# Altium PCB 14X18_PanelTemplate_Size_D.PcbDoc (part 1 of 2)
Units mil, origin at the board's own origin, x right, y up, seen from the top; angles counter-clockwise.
Board outline 18000 x 14000 mil, 2 copper layers (Top Layer, Bottom Layer); 52 components, 1 nets, 312 pads, 0 vias.
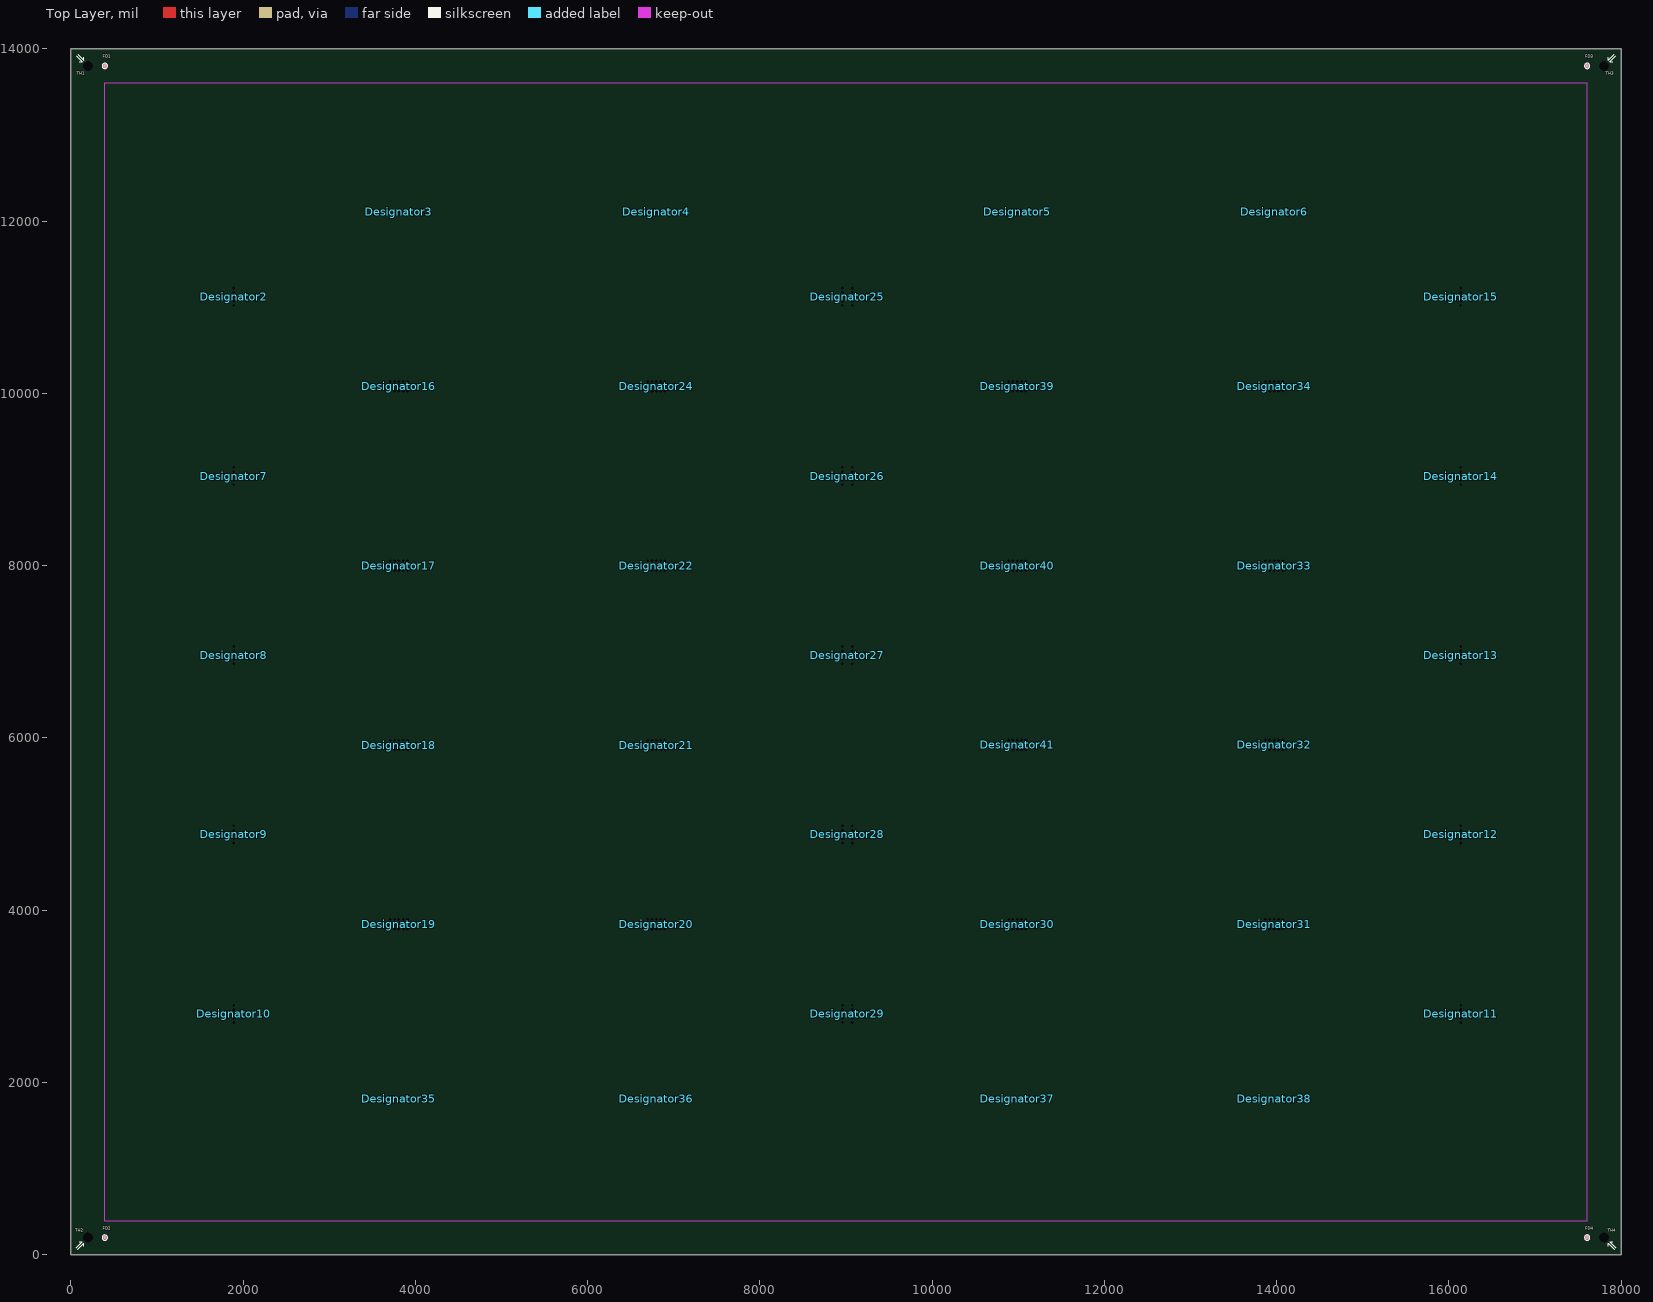
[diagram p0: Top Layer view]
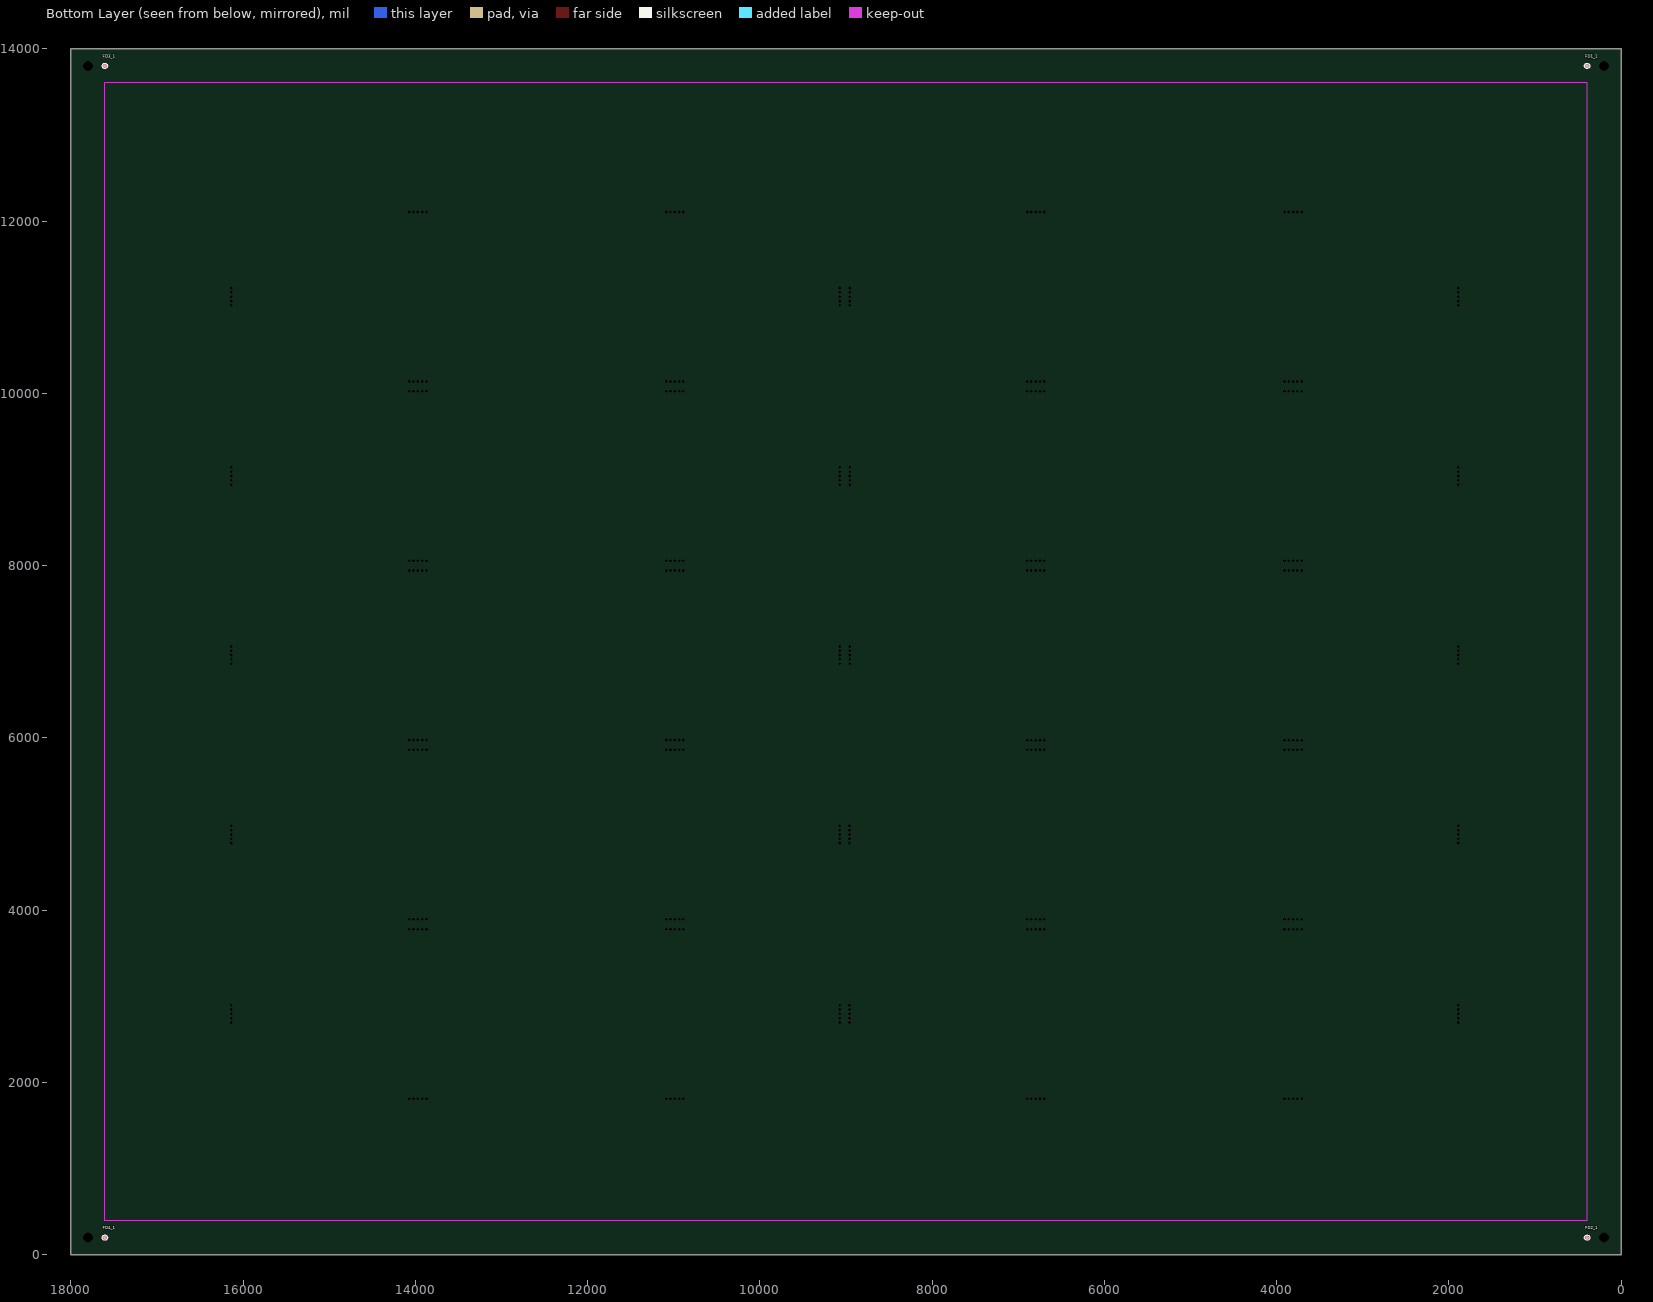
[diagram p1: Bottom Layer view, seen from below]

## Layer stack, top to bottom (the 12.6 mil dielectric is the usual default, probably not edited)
Top Solder: solder mask 0.4, Solder Resist, Dk 3.5
Top Layer: signal copper 1.4
Dielectric1: core 12.6, FR-4, Dk 4.8
Bottom Layer: signal copper 1.4
Bottom Solder: solder mask 0.4, Solder Resist, Dk 3.5

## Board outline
0,0 18000,0 18000,14000 0,14000

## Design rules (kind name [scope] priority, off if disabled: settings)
Clearance [All] p1: gap=1 ignorepadtopadclearanceinfootprint=FALSE except(0: Arc-Hole Track-Hole SMDPad-Hole THPad-Hole Via-Hole Fill-Hole Poly-Hole Region-Hole Text-Hole)
PolygonConnect [All] p1: connectstyle=Relief reliefconductorwidth=10 reliefentries=4 polygonreliefangle="90 Angle" airgapwidth=10
RoutingVias [All] p1: holewidth=28 width=50 viastyle="Through Hole" minholewidth=28 minwidth=50 maxholewidth=28 maxwidth=50
SilkToSolderMaskClearance SilkscreenOverComponentPads [IsPad] p1: minsilkscreentomaskgap=2 clearancetoexposedcopper=TRUE
SolderMaskExpansion [All] p1: expansion=4 istentingtop=FALSE
Width [All] p1: maxlimit=10 minlimit=10 preferedwidth=10
29 further rules are at their usual default settings.

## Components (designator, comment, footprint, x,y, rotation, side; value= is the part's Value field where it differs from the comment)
Designator2 "Comment" SINGLE_SIDE_BREAKOUT 1834.77,11004.17 r270 top
Designator3 "Comment" SINGLE_SIDE_BREAKOUT 3688,12163.66 r180 top
Designator4 "Comment" SINGLE_SIDE_BREAKOUT 6677.05,12163.66 r180 top
Designator5 "Comment" SINGLE_SIDE_BREAKOUT 10868.16,12163.66 r180 top
Designator6 "Comment" SINGLE_SIDE_BREAKOUT 13851.85,12163.66 r180 top
Designator7 "Comment" SINGLE_SIDE_BREAKOUT 1834.77,8920.96 r270 top
Designator8 "Comment" SINGLE_SIDE_BREAKOUT 1834.77,6841.61 r270 top
Designator9 "Comment" SINGLE_SIDE_BREAKOUT 1834.77,4758.4 r270 top
Designator10 "Comment" SINGLE_SIDE_BREAKOUT 1834.77,2675.18 r270 top
Designator11 "Comment" SINGLE_SIDE_BREAKOUT 16195,2915.18 r90 top
Designator12 "Comment" SINGLE_SIDE_BREAKOUT 16195,4998.4 r90 top
Designator13 "Comment" SINGLE_SIDE_BREAKOUT 16195,7081.61 r90 top
Designator14 "Comment" SINGLE_SIDE_BREAKOUT 16195,9160.96 r90 top
Designator15 "Comment" SINGLE_SIDE_BREAKOUT 16195,11244.17 r90 top
Designator16 "Comment" DOUBLE_SIDE_BREAKOUT 3688,10082.47 r180 top
Designator17 "Comment" DOUBLE_SIDE_BREAKOUT 3688,8000.28 r180 top
Designator18 "Comment" DOUBLE_SIDE_BREAKOUT 3688,5917.1 r180 top
Designator19 "Comment" DOUBLE_SIDE_BREAKOUT 3688,3835.91 r180 top
Designator20 "Comment" DOUBLE_SIDE_BREAKOUT 6677.05,3835.91 r180 top
Designator21 "Comment" DOUBLE_SIDE_BREAKOUT 6677.05,5917.1 r180 top
Designator22 "Comment" DOUBLE_SIDE_BREAKOUT 6677.05,8000.28 r180 top
Designator24 "Comment" DOUBLE_SIDE_BREAKOUT 6677.05,10082.47 r180 top
Designator25 "Comment" DOUBLE_SIDE_BREAKOUT 9014.38,11004.17 r270 top
Designator26 "Comment" DOUBLE_SIDE_BREAKOUT 9014.38,8920.96 r270 top
Designator27 "Comment" DOUBLE_SIDE_BREAKOUT 9014.38,6841.61 r270 top
Designator28 "Comment" DOUBLE_SIDE_BREAKOUT 9015.38,4758.4 r270 top
Designator29 "Comment" DOUBLE_SIDE_BREAKOUT 9015.38,2675.18 r270 top
Designator30 "Comment" DOUBLE_SIDE_BREAKOUT 10868.16,3835.91 r180 top
Designator31 "Comment" DOUBLE_SIDE_BREAKOUT 13851.85,3835.91 r180 top
Designator32 "Comment" DOUBLE_SIDE_BREAKOUT 13851.85,5918.09 r180 top
Designator33 "Comment" DOUBLE_SIDE_BREAKOUT 13851.85,8000.28 r180 top
Designator34 "Comment" DOUBLE_SIDE_BREAKOUT 13851.85,10082.47 r180 top
Designator35 "Comment" SINGLE_SIDE_BREAKOUT 3928,1753.72 r0 top
Designator36 "Comment" SINGLE_SIDE_BREAKOUT 6917.05,1753.72 r0 top
Designator37 "Comment" SINGLE_SIDE_BREAKOUT 11108.16,1753.72 r0 top
Designator38 "Comment" SINGLE_SIDE_BREAKOUT 14091.85,1753.72 r0 top
Designator39 "Comment" DOUBLE_SIDE_BREAKOUT 10868.16,10082.47 r180 top
Designator40 "Comment" DOUBLE_SIDE_BREAKOUT 10868.16,7999.29 r180 top
Designator41 "Comment" DOUBLE_SIDE_BREAKOUT 10868.16,5918.09 r180 top
Designator42 "Comment" V_SCORE_DETAIL 22521.01,13086.94 r0 top
FD1 "Comment" FD_1.20MM 393.7,13803.15 r0 top
FD1_1 "Comment" FD_1.20mm 393.7,13803.15 r0 bottom
FD2 "Comment" FD_1.20MM 393.7,196.85 r0 top
FD2_1 "Comment" FD_1.20mm 393.7,196.85 r0 bottom
FD3 "Comment" FD_1.20MM 17606.3,13803.15 r0 top
FD3_1 "Comment" FD_1.20mm 17606.3,13803.15 r0 bottom
FD4 "Comment" FD_1.20MM 17606.3,196.85 r0 top
FD4_1 "Comment" FD_1.20mm 17606.3,196.85 r0 bottom
TH1 "Comment" TH_3mm 196.85,13803.15 r135 top
TH2 "Comment" TH_3mm 196.85,196.85 r225 top
TH3 "Comment" TH_3mm 17803.15,13803.15 r45 top
TH4 "Comment" TH_3mm 17803.15,196.85 r315 top

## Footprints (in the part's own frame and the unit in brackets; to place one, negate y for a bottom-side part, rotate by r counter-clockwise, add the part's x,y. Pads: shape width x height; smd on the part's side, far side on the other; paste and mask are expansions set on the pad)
DOUBLE_SIDE_BREAKOUT [mil] "Rout Tool Diameter 93 mil Slice Track 240 Mil"
  round 0 hole 31 unplated: 0(-220,-56.5) 0(-220,56.5) 0(-170,-56.5) 0(-170,56.5) 0(-120,-56.5) 0(-120,56.5) 0(-70,-56.5) 0(-70,56.5) 0(-20,56.5) 0(-20,-56.5)
FD_1.20MM [mm] "1.20 mm Fiducial"
  round 1.2 smd paste+0 mask+0.102: 0(0,0)
  Keep-Out Layer circle w0.127: c0,0 r0.635
  silkscreen extent -0.78,-0.79 0.79,0.79
FD_1.20mm [mm] "1.20 mm Fiducial"
  round 1.2 smd paste+0 mask+0.102: 0(0,0)
  Keep-Out Layer circle w0.127: c0,0 r0.635
  silkscreen extent -0.78,-0.79 0.79,0.79
SINGLE_SIDE_BREAKOUT [mil] "Rout Tool Diameter 93 mil Slice Track 240 Mil"
  round 0 hole 31 unplated: 0(-220,56.5) 0(-170,56.5) 0(-120,56.5) 0(-70,56.5) 0(-20,56.5)
TH_3mm [mm] "3 mm Tooling Hole"
  round 0 hole 3 unplated paste+0: 0(0,0)
  silkscreen extent 2.03,-0.89 4.57,0.89
V_SCORE_DETAIL [mil]

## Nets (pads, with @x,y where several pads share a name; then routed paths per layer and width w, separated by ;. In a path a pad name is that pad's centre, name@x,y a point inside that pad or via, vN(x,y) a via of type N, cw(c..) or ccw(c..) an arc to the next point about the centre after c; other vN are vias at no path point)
NET1: 
pads on no net: Designator2.0 Designator3.0 Designator4.0 Designator5.0 Designator6.0 Designator7.0 Designator8.0 Designator9.0 Designator10.0 Designator11.0 Designator12.0 Designator13.0 Designator14.0 Designator15.0 Designator16.0 Designator17.0 Designator18.0 Designator19.0 Designator20.0 Designator21.0 Designator22.0 Designator24.0 Designator25.0 Designator26.0 Designator27.0 Designator28.0 Designator29.0 Designator30.0 Designator31.0 Designator32.0 Designator33.0 Designator34.0 Designator35.0 Designator36.0 Designator37.0 Designator38.0 Designator39.0 Designator40.0 Designator41.0 FD1.0 FD1_1.0 FD2.0 FD2_1.0 FD3.0 FD3_1.0 FD4.0 FD4_1.0 TH1.0 TH2.0 TH3.0 TH4.0

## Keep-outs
Keep-Out Layer:
  lines w1: 393.7,393.7 17606.3,393.7 17606.3,13606.3 393.7,13606.3 393.7,393.7
  text "KEEP OUT" at 2000,13675.2 h400
  text "KEEP OUT" at 8100,13675.2 h400
  text "KEEP OUT" at 14200,13675.2 h400
  text "KEEP OUT" at 68.9,11000 h400 r270
  text "KEEP OUT" at 17675.2,11000 h400 r270
  text "KEEP OUT" at 68.9,4800 h400 r270
  text "KEEP OUT" at 17675.2,4800 h400 r270
  text "KEEP OUT" at 2000,68.9 h400
  text "KEEP OUT" at 8100,68.9 h400
  text "KEEP OUT" at 14200,68.9 h400

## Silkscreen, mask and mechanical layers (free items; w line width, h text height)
1_BOARD_OUTLINE:
  the board outline again, w1
Route Tool Path:
  drawing of 180 lines, arcs and shapes, not listed
26_PANEL_DIMENSION:
  lines w10: 17606.3,13803.15 17607.15,13803.15
27_PANEL_FABRICATION_NOTES:
  lines w10: -4.69,1863.04 18093.96,1863.04 ; -4.69,3851.23 18093.96,3851.23 ; -4.69,3945.65 18093.96,3945.65 ; -4.69,5933.84 18093.96,5933.84 ; -4.69,6028.26 18093.96,6028.26 ; -4.69,8016.45 18093.96,8016.45 ; -4.69,8110.88 18093.96,8110.88 ; -4.69,10099.06 18093.96,10099.06 ; -4.69,10193.49 18093.96,10193.49 ; -4.69,12181.68 18093.96,12181.68 ; 1963.96,6.04 1963.96,14106.04 ; 9050.58,6.04 9050.58,14106.04 ; 9145,6.04 9145,14106.04 ; 16231.61,6.04 16231.61,14106.04 ; 17607.15,13803.15 18226,14422 18893,14422 ; 17803.15,13803.15 18707.85,13803.15 18848.85,13803.15 18892.85,13803.15 ; 1875.97,14148.24 1875.97,14325.24 2053.97,14325.24 2053.97,14148.24 1875.97,14148.24 ; 8962.59,14148.24 8962.59,14325.24 9140.59,14325.24 9140.59,14148.24 8962.59,14148.24 ; 9057.01,14148.24 9057.01,14325.24 9235.01,14325.24 9235.01,14148.24 9057.01,14148.24 ; 16143.62,14148.24 16321.62,14148.24 16321.62,14325.24 16143.62,14325.24 16143.62,14148.24 ; 18127.26,3812.36 18305.26,3812.36 18305.26,3989.36 18127.26,3989.36 18127.26,3812.36 ; 18127.26,5894.97 18305.26,5894.97 18305.26,6071.97 18127.26,6071.97 18127.26,5894.97 ; 18127.26,7977.59 18305.26,7977.59 18305.26,8154.59 18127.26,8154.59 18127.26,7977.59 ; 18127.26,10060.2 18127.26,10237.2 18305.26,10237.2 18305.26,10060.2 18127.26,10060.2 ; 18131.49,1782.63 18131.49,1959.63 18309.49,1959.63 18309.49,1782.63 18131.49,1782.63 ; 18131.49,12101.27 18309.49,12101.27 18309.49,12278.27 18131.49,12278.27 18131.49,12101.27 ; 18939,13722 19117,13722 19117,13899 18939,13899 18939,13722 ; 18939,14336 18939,14513 19117,14513 19117,14336 18939,14336 ; 21413.7,14319.34 21591.7,14319.34 21591.7,14496.34 21413.7,14496.34 21413.7,14319.34 ; 21415.86,14045.84 21593.86,14045.84 21593.86,14222.84 21415.86,14222.84 21415.86,14045.84 ; 21420.72,13789.94 21420.72,13966.94 21598.72,13966.94 21598.72,13789.94 21420.72,13789.94
  text "2" at 18992.31,14380.84 h180.44
  text "3" at 1938.57,14190.77 h180.44
  text "3" at 9025.18,14190.77 h180.44
  text "3" at 9119.61,14190.77 h180.44
  text "3" at 16206.22,14190.77 h180.44
  text "N" at 21372.19,14099.21 h82.42
  text "O" at 21416.91,14099.21 h82.42
  text "T" at 21466.1,14099.21 h82.42
  text "E" at 21501.87,14099.21 h82.42
  text "S" at 21537.64,14099.21 h82.42
  text "U" at 21586.83,14099.21 h82.42
  text "N" at 21631.55,14099.21 h82.42
  text "L" at 21676.27,14099.21 h82.42
  text "E" at 21707.57,14099.21 h82.42
  text "S" at 21743.35,14099.21 h82.42
  text "S" at 21774.65,14099.21 h82.42
  text "O" at 21823.84,14099.21 h82.42
  text "T" at 21873.03,14099.21 h82.42
  text "H" at 21908.81,14099.21 h82.42
  text "E" at 21953.53,14099.21 h82.42
  text "R" at 21989.3,14099.21 h82.42
  text "W" at 22029.55,14099.21 h82.42
  text "I" at 22092.15,14099.21 h82.42
  text "S" at 22110.04,14099.21 h82.42
  text "E" at 22141.34,14099.21 h82.42
  text "S" at 22195,14099.21 h82.42
  text "P" at 22226.31,14099.21 h82.42
  text "E" at 22262.08,14099.21 h82.42
  text "C" at 22297.86,14099.21 h82.42
  text "I" at 22338.1,14099.21 h82.42
  text "F" at 22355.99,14099.21 h82.42
  text "I" at 22387.29,14099.21 h82.42
  text "E" at 22405.18,14099.21 h82.42
  text "D" at 22440.95,14099.21 h82.42
  text ":" at 22485.67,14099.21 h82.42
  text "1" at 21407.89,14005.3 h82.42
  text "T" at 21501.62,14005.3 h82.42
  text "O" at 21537.4,14005.3 h82.42
  text "O" at 21586.59,14005.3 h82.42
  text "L" at 21635.78,14005.3 h82.42
  text "I" at 21667.08,14005.3 h82.42
  text "N" at 21684.97,14005.3 h82.42
  text "G" at 21729.68,14005.3 h82.42
  text "H" at 21792.29,14005.3 h82.42
  text "O" at 21837.01,14005.3 h82.42
  text "L" at 21886.2,14005.3 h82.42
  text "E" at 21917.5,14005.3 h82.42
  text "3" at 21971.16,14005.3 h82.42
  text "." at 22006.94,14005.3 h82.42
  text "0" at 22024.82,14005.3 h82.42
  text "0" at 22060.6,14005.3 h82.42
  text "M" at 22114.26,14005.3 h82.42
  text "M" at 22172.39,14005.3 h82.42
  text "O" at 22248.42,14005.3 h82.42
  text "N" at 22297.61,14005.3 h82.42
  text "O" at 22342.32,14005.3 h82.42
  text "-" at 22391.51,14005.3 h82.42
  text "P" at 22413.87,14005.3 h82.42
  text "L" at 22449.65,14005.3 h82.42
  text "A" at 22480.95,14005.3 h82.42
  text "T" at 22521.2,14005.3 h82.42
  text "E" at 22556.97,14005.3 h82.42
  text "D" at 22592.75,14005.3 h82.42
  text "4" at 22655.35,14005.3 h82.42
  text "P" at 22709.01,14005.3 h82.42
  text "L" at 22744.79,14005.3 h82.42
  text "A" at 22776.09,14005.3 h82.42
  text "C" at 22816.34,14005.3 h82.42
  text "E" at 22856.58,14005.3 h82.42
  text "S" at 22892.36,14005.3 h82.42
  text "2" at 21407.89,13911.4 h82.42
  text "F" at 21501.62,13911.4 h82.42
  text "I" at 21532.92,13911.4 h82.42
  text "D" at 21550.81,13911.4 h82.42
  text "U" at 21595.53,13911.4 h82.42
  text "C" at 21640.25,13911.4 h82.42
  text "I" at 21680.49,13911.4 h82.42
  text "A" at 21698.38,13911.4 h82.42
  text "L" at 21738.63,13911.4 h82.42
  text "1" at 21787.82,13911.4 h82.42
  text "." at 21823.59,13911.4 h82.42
  text "2" at 21841.48,13911.4 h82.42
  text "0" at 21877.25,13911.4 h82.42
  text "M" at 21930.92,13911.4 h82.42
  text "M" at 21989.05,13911.4 h82.42
  text "4" at 22065.07,13911.4 h82.42
  text "P" at 22118.73,13911.4 h82.42
  text "L" at 22154.51,13911.4 h82.42
  text "A" at 22185.81,13911.4 h82.42
  text "C" at 22226.06,13911.4 h82.42
  text "E" at 22266.3,13911.4 h82.42
  text "S" at 22302.08,13911.4 h82.42
  text "3" at 21407.89,13817.49 h82.42
  text "V" at 21501.62,13817.49 h82.42
  text "S" at 21559.75,13817.49 h82.42
  text "C" at 21591.06,13817.49 h82.42
  text "O" at 21631.3,13817.49 h82.42
  text "R" at 21680.49,13817.49 h82.42
  text "E" at 21720.74,13817.49 h82.42
  text "D" at 21774.4,13817.49 h82.42
  text "E" at 21819.12,13817.49 h82.42
  text "T" at 21854.89,13817.49 h82.42
  text "A" at 21890.67,13817.49 h82.42
  text "I" at 21930.92,13817.49 h82.42
  text "L" at 21948.8,13817.49 h82.42
  text "1" at 19001.6,13764.53 h180.44
  text "3" at 18194.09,12143.8 h180.44
  text "3" at 18189.86,10102.73 h180.44
  text "3" at 18189.86,8020.12 h180.44
  text "3" at 18189.86,5937.5 h180.44
  text "3" at 18189.86,3854.89 h180.44
  text "3" at 18194.09,1825.16 h180.44
29_PANEL_TITLE_BLOCK:
  drawing of 109 lines, arcs and shapes, not listed
  text "DWG. NO." at 27305.1,18815 h30
  text "REV:" at 28315.1,18815 h30
  text "1" at 1525,18775 h250
  text "2" at 9900,18775 h250
  text "3" at 18250,18775 h250
  text "4" at 26600,18775 h250
  text ".PCB_DWG_NO" at 27520,18725 h50
  text ".PCB_REV" at 28330,18725 h50
  text "T" at -2688,18627.61 h76
  text "H" at -2644.65,18627.61 h76
  text "I" at -2594.64,18627.61 h76
  text "S" at -2574.64,18627.61 h76
  text "D" at -2509.62,18627.61 h76
  text "O" at -2459.61,18627.61 h76
  text "C" at -2404.59,18627.61 h76
  text "U" at -2354.58,18627.61 h76
  text "M" at -2304.57,18627.61 h76
  text "E" at -2246.22,18627.61 h76
  text "N" at -2199.54,18627.61 h76
  text "T" at -2151.2,18627.61 h76
  text "A" at -2087.85,18627.61 h76
  text "N" at -2041.17,18627.61 h76
  text "D" at -1991.16,18627.61 h76
  text "T" at -1922.81,18627.61 h76
  text "H" at -1879.47,18627.61 h76
  text "E" at -1829.45,18627.61 h76
  text "D" at -1764.44,18627.61 h76
  text "A" at -1714.43,18627.61 h76
  text "T" at -1667.75,18627.61 h76
  text "A" at -1626.07,18627.61 h76
  text "D" at -1559.39,18627.61 h76
  text "I" at -1509.37,18627.61 h76
  text "S" at -1491.04,18627.61 h76
  text "C" at -1444.36,18627.61 h76
  text "L" at -1394.35,18627.61 h76
  text "O" at -1356,18627.61 h76
  text "S" at -1300.99,18627.61 h76
  text "E" at -1254.31,18627.61 h76
  text "D" at -1207.63,18627.61 h76
  text "H" at -1139.28,18627.61 h76
  text "E" at -1089.27,18627.61 h76
  text "R" at -1042.59,18627.61 h76
  text "E" at -994.25,18627.61 h76
  text "I" at -947.57,18627.61 h76
  text "N" at -927.57,18627.61 h76
  text "O" at -859.21,18627.61 h76
  text "R" at -804.2,18627.61 h76
  text "REVISIONS" at 28540,18595 h60
  text "H" at -2688,18547.59 h76
  text "E" at -2637.99,18547.59 h76
  text "R" at -2591.31,18547.59 h76
  text "E" at -2541.3,18547.59 h76
  text "W" at -2496.28,18547.59 h76
  text "I" at -2427.93,18547.59 h76
  text "T" at -2409.6,18547.59 h76
  text "H" at -2366.25,18547.59 h76
  text "I" at -2297.9,18547.59 h76
  text "S" at -2277.9,18547.59 h76
  text "T" at -2212.88,18547.59 h76
  text "H" at -2169.54,18547.59 h76
  text "E" at -2119.52,18547.59 h76
  text "P" at -2054.51,18547.59 h76
  text "R" at -2007.83,18547.59 h76
  text "O" at -1957.82,18547.59 h76
  text "P" at -1903.77,18547.59 h76
  text "E" at -1857.09,18547.59 h76
  text "R" at -1810.41,18547.59 h76
  text "T" at -1762.07,18547.59 h76
  text "Y" at -1718.73,18547.59 h76
  text "O" at -1653.71,18547.59 h76
  text "F" at -1600.36,18547.59 h76
  text "A" at -1537.01,18547.59 h76
  text "L" at -1490.34,18547.59 h76
  text "T" at -1453.66,18547.59 h76
  text "I" at -1410.32,18547.59 h76
  text "U" at -1390.31,18547.59 h76
  text "M" at -1340.3,18547.59 h76
  text "L" at -1263.61,18547.59 h76
  text "I" at -1225.27,18547.59 h76
  text "M" at -1205.27,18547.59 h76
  text "I" at -1148.58,18547.59 h76
  text "T" at -1128.58,18547.59 h76
  text "E" at -1085.24,18547.59 h76
  text "D" at -1038.56,18547.59 h76
  text "A" at -970.21,18547.59 h76
  text "N" at -923.53,18547.59 h76
  text "D" at -873.52,18547.59 h76
  text "M" at -803.5,18547.59 h76
  text "A" at -745.15,18547.59 h76
  text "Y" at -700.14,18547.59 h76
  text "ZONE" at 26955,18470 h60
  text "REV" at 27285,18470 h60
  text "DATE" at 29705,18470 h60
  text "B" at -2688,18467.57 h76
  text "E" at -2641.32,18467.57 h76
  text "F" at -2574.64,18467.57 h76
  text "R" at -2531.29,18467.57 h76
  text "E" at -2481.28,18467.57 h76
  text "E" at -2436.27,18467.57 h76
  text "L" at -2389.59,18467.57 h76
  text "Y" at -2351.25,18467.57 h76
  text "D" at -2284.57,18467.57 h76
  text "I" at -2234.55,18467.57 h76
  text "S" at -2216.22,18467.57 h76
  text "T" at -2169.54,18467.57 h76
  text "R" at -2126.88,18467.57 h76
  text "I" at -2078.54,18467.57 h76
  text "B" at -2058.53,18467.57 h76
  text "U" at -2011.86,18467.57 h76
  text "T" at -1961.84,18467.57 h76
  text "E" at -1918.5,18467.57 h76
  text "D" at -1871.82,18467.57 h76
  text "I" at -1803.47,18467.57 h76
  text "N" at -1783.47,18467.57 h76
  text "W" at -1716.78,18467.57 h76
  text "H" at -1648.43,18467.57 h76
  text "O" at -1600.09,18467.57 h76
  text "L" at -1545.07,18467.57 h76
  text "E" at -1506.73,18467.57 h76
  text "." at -1460.05,18467.57 h76
  text "N" at -1421.71,18467.57 h76
  text "O" at -1371.7,18467.57 h76
  text "R" at -1296.68,18467.57 h76
  text "I" at -1248.33,18467.57 h76
  text "G" at -1228.33,18467.57 h76
  text "H" at -1173.32,18467.57 h76
  text "T" at -1124.97,18467.57 h76
  text "S" at -1081.63,18467.57 h76
  text "A" at -1016.61,18467.57 h76
  text "R" at -969.93,18467.57 h76
  text "E" at -919.92,18467.57 h76
  text "DESCRIPTION" at 28300,18465 h60
  text "APPROVED" at 30210,18465 h60
  text "R" at -2688,18387.55 h76
  text "E" at -2637.99,18387.55 h76
  text "S" at -2591.31,18387.55 h76
  text "E" at -2544.63,18387.55 h76
  text "R" at -2497.95,18387.55 h76
  text "V" at -2447.94,18387.55 h76
  text "E" at -2401.26,18387.55 h76
  text "D" at -2354.58,18387.55 h76
  text "O" at -2286.23,18387.55 h76
  text "R" at -2231.22,18387.55 h76
  text "E" at -2161.2,18387.55 h76
  text "X" at -2114.52,18387.55 h76
  text "P" at -2069.51,18387.55 h76
  text "R" at -2022.83,18387.55 h76
  text "E" at -1972.82,18387.55 h76
  text "S" at -1926.14,18387.55 h76
  text "S" at -1879.47,18387.55 h76
  text "O" at -1814.45,18387.55 h76
  text "R" at -1759.44,18387.55 h76
  text "I" at -1691.09,18387.55 h76
  text "M" at -1671.08,18387.55 h76
  text "P" at -1612.73,18387.55 h76
  text "L" at -1566.06,18387.55 h76
  text "I" at -1529.38,18387.55 h76
  text "E" at -1509.37,18387.55 h76
  text "D" at -1462.7,18387.55 h76
  text "W" at -1396.01,18387.55 h76
  text "A" at -1327.66,18387.55 h76
  text "R" at -1280.99,18387.55 h76
  text "A" at -1230.97,18387.55 h76
  text "N" at -1184.29,18387.55 h76
  text "T" at -1135.95,18387.55 h76
  text "E" at -1092.61,18387.55 h76
  text "E" at -1045.93,18387.55 h76
  text "G" at -984.68,18387.55 h76
  text "I" at -929.66,18387.55 h76
  text "V" at -909.66,18387.55 h76
  text "E" at -862.98,18387.55 h76
  text "N" at -816.3,18387.55 h76
  text "." at -767.96,18387.55 h76
  text "A" at 27315,18335 h60
  text "ORIGINAL" at 28375,18335 h60
  text "A" at -2900,15900 h250
  text "A" at 30775,15900 h250
  text "B" at -2900,10550 h250
  text "B" at 30775,10550 h250
  text "C" at -2900,5200 h250
  text "C" at 30775,5200 h250
  text "DWG. NO." at 30815,3744.9 h30 r270
  text ".PCB_DWG_NO" at 30725,3530 h50 r270
  text "REV:" at 30815,2734.9 h30 r270
  text "D" at -2900,-150 h250
  text "D" at 30775,-150 h250
  text "PART NO." at 24750,-1091 h45
  text ".PCB_PART_NUMBER" at 25065,-1091 h45
  text "UNLESS OTHERWISE SPECIFIED DIMENSIONS" at 24770,-1196 h45
  text "APPROVALS" at 26426,-1198.1 h45
  text "DATE" at 27286,-1198.1 h45
  text "2175 SALK AVENUE" at 29505,-1201 h45
  text "AND TOLERANCE ARE IN INCHES AND" at 24825,-1271 h45
  text "DESIGNER:" at 26106,-1278.1 h45
  text "SUITE 200" at 29505,-1291 h45
  text "APPLY TO THE FINISHED PART" at 24935,-1341 h45
  text ".PCB_DESIGNER" at 26426,-1358.1 h60
  text ".PCB_DESIGNER_APP_DATE" at 27156,-1358.1 h50
  text "CARLSBAD, CA 92008" at 29505,-1381.01 h45
  text "TOLERANCE ON:" at 25175,-1466 h45
  text "USA" at 29505,-1471 h45
  text "ENGINEER:" at 26106,-1478.1 h45
  text ".PCB_ENGINEER_APP_DATE" at 27156,-1548.1 h50
  text "2 DEC. PLACE" at 24770,-1556 h40
  text "3 DEC. PLACE" at 25225,-1556 h40
  text "ANGLES" at 25760,-1556 h40
  text ".PCB_ENGINEER" at 26426,-1558.1 h60
  text "TITLE:" at 27620,-1576 h45
  text "CHECKER:" at 26106,-1678.1 h45
  text ".PCB_2_DEC_TOL" at 24825,-1711 h60
  text ".PCB_3_DEC_TOL" at 25260,-1711 h60
  text ".PCB_ANG_TOL" at 25725,-1711 h60
  text ".PCB_TITLE_1" at 27795,-1726 h100
  text ".PCB_CHECKER_APP_DATE" at 27154,-1752.1 h50
  text ".PCB_CHECKER" at 26426,-1758.1 h60
  text "THIRD ANGLE PROJECTION" at 23997,-1771.1 h40
  text "MATERIAL:" at 24770,-1854.1 h45
  text "REFERENCE DOCUMENTS" at 26486,-1898.1 h45
  text "BOM:" at 26106,-1998.1 h45
  text ".PCB_TITLE_2" at 27790,-2021 h100
  text "SEE NOTES" at 25136,-2053.1 h60
  text ".DOC_NO_BOM" at 26426,-2088.1 h60
  text "ASSY DWG:" at 26106,-2188.1 h45
  text ".DOC_NO_ASSY_DWG" at 26426,-2278.1 h60
  text "SIZE:" at 27680,-2311 h45
  text "CAGE CODE:" at 27925,-2311 h45
  text "DWG NO:" at 28925,-2311 h45
  text "REV:" at 30485,-2311 h45
  text "FAB DWG:" at 26106,-2378.1 h45
  text ".PCB_DWG_NO" at 29235,-2451 h100
  text "B" at 27720,-2456 h100
  text ".DOC_NO_FAB_DWG" at 26426,-2463.1 h60
  text ".CAGE_CODE" at 28095,-2466 h100
  text "SCHEMATIC:" at 26106,-2568.1 h45
  text "PRINT DATE:" at 24762,-2569.1 h45
  text "SCALE:" at 27620,-2626 h45
  text "FILE NAME:" at 28225,-2626.1 h45
  text "SHEET:" at 29965,-2626.1 h45
  text ".PRINT_DATE" at 25170,-2638.1 h60
  text ".Printout_Name" at -2644,-2647 h150
  text ".Printout_Name" at -2644,-2647 h150
  text ".Printout_Name" at -2644,-2647 h150
  text ".DOC_NO_SCH_DWG" at 26426,-2658.1 h60
  text ".PCB_FILE_NAME_NO_PATH" at 28568,-2671.1 h60
  text ".PCB_SCALE" at 27890,-2676 h60
  text "OF" at 30415,-2676.1 h45
  text "DOC-104 REV A" at -2700,-2742.1 h20
  text "DOC-104 REV A" at -2700,-2742.1 h20
  text "DOC-104 REV A" at -2700,-2742.1 h20
  text "1" at 1525,-2925 h250
  text "2" at 9900,-2925 h250
  text "3" at 18250,-2925 h250
  text "4" at 26600,-2925 h250
30_PANEL_TITLE_BLOCK_MIRRORED:
  drawing of 109 lines, arcs and shapes, not listed
  text "REV:" at -315.1,18816 h30
  text "DWG. NO." at 694.9,18816 h30
  text "4" at 1400,18776 h250
  text "3" at 9750,18776 h250
  text "2" at 18100,18776 h250
  text "1" at 26475,18776 h250
  text ".PCB_REV" at -330,18726 h50
  text ".PCB_DWG_NO" at 480,18726 h50
  text "R" at 28804.2,18628.61 h76
  text "O" at 28859.22,18628.61 h76
  text "N" at 28927.57,18628.61 h76
  text "I" at 28947.57,18628.61 h76
  text "E" at 28994.25,18628.61 h76
  text "R" at 29042.6,18628.61 h76
  text "E" at 29089.27,18628.61 h76
  text "H" at 29139.29,18628.61 h76
  text "D" at 29207.64,18628.61 h76
  text "E" at 29254.31,18628.61 h76
  text "S" at 29300.99,18628.61 h76
  text "O" at 29356.01,18628.61 h76
  text "L" at 29394.35,18628.61 h76
  text "C" at 29444.36,18628.61 h76
  text "S" at 29491.04,18628.61 h76
  text "I" at 29509.38,18628.61 h76
  text "D" at 29559.39,18628.61 h76
  text "A" at 29626.07,18628.61 h76
  text "T" at 29667.75,18628.61 h76
  text "A" at 29714.43,18628.61 h76
  text "D" at 29764.44,18628.61 h76
  text "E" at 29829.46,18628.61 h76
  text "H" at 29879.47,18628.61 h76
  text "T" at 29922.81,18628.61 h76
  text "D" at 29991.16,18628.61 h76
  text "N" at 30041.17,18628.61 h76
  text "A" at 30087.85,18628.61 h76
  text "T" at 30151.2,18628.61 h76
  text "N" at 30199.55,18628.61 h76
  text "E" at 30246.22,18628.61 h76
  text "M" at 30304.57,18628.61 h76
  text "U" at 30354.58,18628.61 h76
  text "C" at 30404.6,18628.61 h76
  text "O" at 30459.61,18628.61 h76
  text "D" at 30509.62,18628.61 h76
  text "S" at 30574.64,18628.61 h76
  text "I" at 30594.64,18628.61 h76
  text "H" at 30644.66,18628.61 h76
  text "T" at 30688,18628.61 h76
  text "REVISIONS" at -540,18596 h60
  text "Y" at 28700.14,18548.59 h76
  text "A" at 28745.15,18548.59 h76
  text "M" at 28803.5,18548.59 h76
  text "D" at 28873.52,18548.59 h76
  text "N" at 28923.53,18548.59 h76
  text "A" at 28970.21,18548.59 h76
  text "D" at 29038.56,18548.59 h76
  text "E" at 29085.24,18548.59 h76
  text "T" at 29128.58,18548.59 h76
  text "I" at 29148.59,18548.59 h76
  text "M" at 29205.27,18548.59 h76
  text "I" at 29225.27,18548.59 h76
  text "L" at 29263.62,18548.59 h76
  text "M" at 29340.3,18548.59 h76
  text "U" at 29390.31,18548.59 h76
  text "I" at 29410.32,18548.59 h76
  text "T" at 29453.66,18548.59 h76
  text "L" at 29490.34,18548.59 h76
  text "A" at 29537.02,18548.59 h76
  text "F" at 29600.36,18548.59 h76
  text "O" at 29653.71,18548.59 h76
  text "Y" at 29718.73,18548.59 h76
  text "T" at 29762.07,18548.59 h76
  text "R" at 29810.42,18548.59 h76
  text "E" at 29857.09,18548.59 h76
  text "P" at 29903.77,18548.59 h76
  text "O" at 29957.82,18548.59 h76
  text "R" at 30007.83,18548.59 h76
  text "P" at 30054.51,18548.59 h76
  text "E" at 30119.53,18548.59 h76
  text "H" at 30169.54,18548.59 h76
  text "T" at 30212.88,18548.59 h76
  text "S" at 30277.9,18548.59 h76
  text "I" at 30297.9,18548.59 h76
  text "H" at 30366.25,18548.59 h76
  text "T" at 30409.6,18548.59 h76
  text "I" at 30427.94,18548.59 h76
  text "W" at 30496.29,18548.59 h76
  text "E" at 30541.3,18548.59 h76
  text "R" at 30591.31,18548.59 h76
  text "E" at 30637.99,18548.59 h76
  text "H" at 30688,18548.59 h76
  text "DATE" at -1705,18471 h60
  text "REV" at 715,18471 h60
  text "ZONE" at 1045,18471 h60
  text "E" at 28919.92,18468.57 h76
  text "R" at 28969.93,18468.57 h76
  text "A" at 29016.61,18468.57 h76
  text "S" at 29081.63,18468.57 h76
  text "T" at 29124.97,18468.57 h76
  text "H" at 29173.32,18468.57 h76
  text "G" at 29228.33,18468.57 h76
  text "I" at 29248.34,18468.57 h76
  text "R" at 29296.68,18468.57 h76
  text "O" at 29371.7,18468.57 h76
  text "N" at 29421.71,18468.57 h76
  text "." at 29460.06,18468.57 h76
  text "E" at 29506.73,18468.57 h76
  text "L" at 29545.08,18468.57 h76
  text "O" at 29600.09,18468.57 h76
  text "H" at 29648.44,18468.57 h76
  text "W" at 29716.79,18468.57 h76
  text "N" at 29783.47,18468.57 h76
  text "I" at 29803.47,18468.57 h76
  text "D" at 29871.82,18468.57 h76
  text "E" at 29918.5,18468.57 h76
  text "T" at 29961.85,18468.57 h76
  text "U" at 30011.86,18468.57 h76
  text "B" at 30058.54,18468.57 h76
  text "I" at 30078.54,18468.57 h76
  text "R" at 30126.89,18468.57 h76
  text "T" at 30169.54,18468.57 h76
  text "S" at 30216.22,18468.57 h76
  text "I" at 30234.56,18468.57 h76
  text "D" at 30284.57,18468.57 h76
  text "Y" at 30351.25,18468.57 h76
  text "L" at 30389.59,18468.57 h76
  text "E" at 30436.27,18468.57 h76
  text "E" at 30481.28,18468.57 h76
  text "R" at 30531.29,18468.57 h76
  text "F" at 30574.64,18468.57 h76
  text "E" at 30641.32,18468.57 h76
  text "B" at 30688,18468.57 h76
  text "APPROVED" at -2210,18466 h60
  text "DESCRIPTION" at -300,18466 h60
  text "." at 28767.96,18388.55 h76
  text "N" at 28816.3,18388.55 h76
  text "E" at 28862.98,18388.55 h76
  text "V" at 28909.66,18388.55 h76
  text "I" at 28929.66,18388.55 h76
  text "G" at 28984.68,18388.55 h76
  text "E" at 29045.93,18388.55 h76
  text "E" at 29092.61,18388.55 h76
  text "T" at 29135.95,18388.55 h76
  text "N" at 29184.3,18388.55 h76
  text "A" at 29230.97,18388.55 h76
  text "R" at 29280.99,18388.55 h76
  text "A" at 29327.67,18388.55 h76
  text "W" at 29396.02,18388.55 h76
  text "D" at 29462.7,18388.55 h76
  text "E" at 29509.38,18388.55 h76
  text "I" at 29529.38,18388.55 h76
  text "L" at 29566.06,18388.55 h76
  text "P" at 29612.74,18388.55 h76
  text "M" at 29671.08,18388.55 h76
  text "I" at 29691.09,18388.55 h76
  text "R" at 29759.44,18388.55 h76
  text "O" at 29814.45,18388.55 h76
  text "S" at 29879.47,18388.55 h76
  text "S" at 29926.15,18388.55 h76
  text "E" at 29972.82,18388.55 h76
  text "R" at 30022.84,18388.55 h76
  text "P" at 30069.51,18388.55 h76
  text "X" at 30114.53,18388.55 h76
  text "E" at 30161.2,18388.55 h76
  text "R" at 30231.22,18388.55 h76
  text "O" at 30286.23,18388.55 h76
  text "D" at 30354.58,18388.55 h76
  text "E" at 30401.26,18388.55 h76
  text "V" at 30447.94,18388.55 h76
  text "R" at 30497.95,18388.55 h76
  text "E" at 30544.63,18388.55 h76
  text "S" at 30591.31,18388.55 h76
  text "E" at 30637.99,18388.55 h76
  text "R" at 30688,18388.55 h76
  text "ORIGINAL" at -375,18336 h60
  text "A" at 685,18336 h60
  text "A" at -2775,15901 h250
  text "A" at 30900,15901 h250
  text "B" at -2775,10551 h250
  text "B" at 30900,10551 h250
  text "C" at -2775,5201 h250
  text "C" at 30900,5201 h250
  text "DWG. NO." at -2815,3745.9 h30 r90
  text ".PCB_DWG_NO" at -2725,3531 h50 r90
  text "REV:" at -2815,2735.9 h30 r90
  text "D" at -2775,-149 h250
  text "D" at 30900,-149 h250
  text ".PCB_PART_NUMBER" at 2935,-1090 h45
  text "PART NO." at 3250,-1090 h45
  text "UNLESS OTHERWISE SPECIFIED DIMENSIONS" at 3230,-1195 h45
  text "DATE" at 714,-1197.1 h45
  text "APPROVALS" at 1574,-1197.1 h45
  text "2175 SALK AVENUE" at -1505,-1200 h45
  text "AND TOLERANCE ARE IN INCHES AND" at 3175,-1270 h45
  text "DESIGNER:" at 1894,-1277.1 h45
  text "SUITE 200" at -1505,-1290 h45
  text "APPLY TO THE FINISHED PART" at 3065,-1340 h45
  text ".PCB_DESIGNER_APP_DATE" at 844,-1357.1 h50
  text ".PCB_DESIGNER" at 1574,-1357.1 h60
  text "CARLSBAD, CA 92008" at -1505,-1380.01 h45
  text "TOLERANCE ON:" at 2825,-1465 h45
  text "USA" at -1505,-1470 h45
  text "ENGINEER:" at 1894,-1477.1 h45
  text ".PCB_ENGINEER_APP_DATE" at 844,-1547.1 h50
  text "ANGLES" at 2240,-1555 h40
  text "3 DEC. PLACE" at 2775,-1555 h40
  text "2 DEC. PLACE" at 3230,-1555 h40
  text ".PCB_ENGINEER" at 1574,-1557.1 h60
  text "TITLE:" at 380,-1575 h45
  text "CHECKER:" at 1894,-1677.1 h45
  text ".PCB_ANG_TOL" at 2275,-1710 h60
  text ".PCB_3_DEC_TOL" at 2740,-1710 h60
  text ".PCB_2_DEC_TOL" at 3175,-1710 h60
  text ".PCB_TITLE_1" at 205,-1725 h100
  text ".PCB_CHECKER_APP_DATE" at 846,-1751.1 h50
  text ".PCB_CHECKER" at 1574,-1757.1 h60
  text "THIRD ANGLE PROJECTION" at 4003,-1770.1 h40
  text "MATERIAL:" at 3230,-1853.1 h45
  text "REFERENCE DOCUMENTS" at 1514,-1897.1 h45
  text "BOM:" at 1894,-1997.1 h45
  text ".PCB_TITLE_2" at 210,-2020 h100
  text "SEE NOTES" at 2864,-2052.1 h60
  text ".DOC_NO_BOM" at 1574,-2087.1 h60
  text "ASSY DWG:" at 1894,-2187.1 h45
  text ".DOC_NO_ASSY_DWG" at 1574,-2277.1 h60
  text "REV:" at -2485,-2310 h45
  text "DWG NO:" at -925,-2310 h45
  text "CAGE CODE:" at 75,-2310 h45
  text "SIZE:" at 320,-2310 h45
  text "FAB DWG:" at 1894,-2377.1 h45
  text ".PCB_DWG_NO" at -1235,-2450 h100
  text "B" at 280,-2455 h100
  text ".DOC_NO_FAB_DWG" at 1574,-2462.1 h60
  text ".CAGE_CODE" at -95,-2465 h100
  text "SCHEMATIC:" at 1894,-2567.1 h45
  text "PRINT DATE:" at 3238,-2568.1 h45
  text "SHEET:" at -1965,-2625.1 h45
  text "FILE NAME:" at -225,-2625.1 h45
  text "SCALE:" at 380,-2625 h45
  text ".PRINT_DATE" at 2830,-2637.1 h60
  text ".Printout_Name" at 30644,-2646 h150
  text ".Printout_Name" at 30644,-2646 h150
  text ".Printout_Name" at 30644,-2646 h150
  text ".DOC_NO_SCH_DWG" at 1574,-2657.1 h60
  text ".PCB_FILE_NAME_NO_PATH" at -568,-2670.1 h60
  text "OF" at -2415,-2675.1 h45
  text ".PCB_SCALE" at 110,-2675 h60
  text "DOC-104 REV A" at 30700,-2741.1 h20
  text "DOC-104 REV A" at 30700,-2741.1 h20
  text "DOC-104 REV A" at 30700,-2741.1 h20
  text "4" at 1400,-2924 h250
  text "3" at 9750,-2924 h250
  text "2" at 18100,-2924 h250
  text "1" at 26475,-2924 h250
31_PANEL_CONTINUATION_BLOCK:
  lines w1: -3000,-3000 31000,-3000 31000,19000 -3000,19000 -3000,-3000 ; -2700,-2700 -2700,18700 30700,18700 30700,-2700 -2700,-2700
  lines w5: 26200,-2701 30700,-2701 30700,-1501 ; 26905,18175 30698,18175 ; 26905,18305 30698,18305 ; 26905,18435 30698,18435 ; 26905,18565 30698,18565 ; 26905,18695 26905,18045 30698,18045 ; 27205,18045 27205,18565 ; 27290,18700 27290,18849 28400,18849 28400,18700 ; 27505,18045 27505,18565 ; 27595,-2701 27595,-2551 ; 27900,-2551 27900,-2236 ; 28200,-2701 28200,-2551 ; 28290,18700 28290,18849 ; 28900,-2551 28900,-2236 ; 29505,18045 29505,18565 ; 29940,-2701.1 29940,-2551.1 ; 30105,18045 30105,18565 ; 30400,-2551 30400,-2236 ; 30700,-2551 27595,-2551 ; 30700,-2236 27595,-2236 27595,-2551 ; 30700,2650 30849,2650 30849,3760 30700,3760 ; 30700,2760 30849,2760 ; -2700,-2700 177,-2700 ; -2700,-2700 -2700,-2504 ; -2700,-2700 177,-2700 ; -2700,-2700 -2700,-2504 ; -2700,-2700 -2700,-2504 ; -2700,-2700 177,-2700 ; -2700,-2504 177,-2504 ; -2700,-2504 177,-2504 ; -2700,-2504 177,-2504 ; 177,-2700 177,-2504 ; 177,-2700 177,-2504 ; 177,-2700 177,-2504 ; -2700,18370 -2700,18700 -640,18700 -640,18370 -2700,18370
  lines w10: -3000,2650 -2700,2650 ; -3000,8000 -2700,8000 ; -3000,13350 -2700,13350 ; 5650,-3000 5650,-2700 ; 5650,18700 5650,19000 ; 14000,-3000 14000,-2700 ; 14000,18700 14000,19000 ; 22350,-3000 22350,-2700 ; 22350,18700 22350,19000 ; 30700,2650 31000,2650 ; 30700,8000 31000,8000 ; 30700,13350 31000,13350
  text "DWG. NO." at 27305.1,18815 h30
  text "REV:" at 28315.1,18815 h30
  text "1" at 1525,18775 h250
  text "2" at 9900,18775 h250
  text "3" at 18250,18775 h250
  text "4" at 26600,18775 h250
  text ".PCB_DWG_NO" at 27520,18725 h50
  text ".PCB_REV" at 28330,18725 h50
  text "T" at -2688,18627.61 h76
  text "H" at -2644.65,18627.61 h76
  text "I" at -2594.64,18627.61 h76
  text "S" at -2574.64,18627.61 h76
  text "D" at -2509.62,18627.61 h76
  text "O" at -2459.61,18627.61 h76
  text "C" at -2404.59,18627.61 h76
  text "U" at -2354.58,18627.61 h76
  text "M" at -2304.57,18627.61 h76
  text "E" at -2246.22,18627.61 h76
  text "N" at -2199.54,18627.61 h76
  text "T" at -2151.2,18627.61 h76
  text "A" at -2087.85,18627.61 h76
  text "N" at -2041.17,18627.61 h76
  text "D" at -1991.16,18627.61 h76
  text "T" at -1922.81,18627.61 h76
  text "H" at -1879.47,18627.61 h76
  text "E" at -1829.45,18627.61 h76
  text "D" at -1764.44,18627.61 h76
  text "A" at -1714.43,18627.61 h76
  text "T" at -1667.75,18627.61 h76
  text "A" at -1626.07,18627.61 h76
  text "D" at -1559.39,18627.61 h76
  text "I" at -1509.37,18627.61 h76
  text "S" at -1491.04,18627.61 h76
  text "C" at -1444.36,18627.61 h76
  text "L" at -1394.35,18627.61 h76
  text "O" at -1356,18627.61 h76
  text "S" at -1300.99,18627.61 h76
  text "E" at -1254.31,18627.61 h76
  text "D" at -1207.63,18627.61 h76
  text "H" at -1139.28,18627.61 h76
  text "E" at -1089.27,18627.61 h76
  text "R" at -1042.59,18627.61 h76
  text "E" at -994.25,18627.61 h76
  text "I" at -947.57,18627.61 h76
  text "N" at -927.57,18627.61 h76
  text "O" at -859.21,18627.61 h76
  text "R" at -804.2,18627.61 h76
  text "REVISIONS" at 28540,18595 h60
  text "H" at -2688,18547.59 h76
  text "E" at -2637.99,18547.59 h76
  text "R" at -2591.31,18547.59 h76
  text "E" at -2541.3,18547.59 h76
  text "W" at -2496.28,18547.59 h76
  text "I" at -2427.93,18547.59 h76
  text "T" at -2409.6,18547.59 h76
  text "H" at -2366.25,18547.59 h76
  text "I" at -2297.9,18547.59 h76
  text "S" at -2277.9,18547.59 h76
  text "T" at -2212.88,18547.59 h76
  text "H" at -2169.54,18547.59 h76
  text "E" at -2119.52,18547.59 h76
  text "P" at -2054.51,18547.59 h76
  text "R" at -2007.83,18547.59 h76
  text "O" at -1957.82,18547.59 h76
  text "P" at -1903.77,18547.59 h76
  text "E" at -1857.09,18547.59 h76
  text "R" at -1810.41,18547.59 h76
  text "T" at -1762.07,18547.59 h76
  text "Y" at -1718.73,18547.59 h76
  text "O" at -1653.71,18547.59 h76
  text "F" at -1600.36,18547.59 h76
  text "A" at -1537.01,18547.59 h76
  text "L" at -1490.34,18547.59 h76
  text "T" at -1453.66,18547.59 h76
  text "I" at -1410.32,18547.59 h76
  text "U" at -1390.31,18547.59 h76
  text "M" at -1340.3,18547.59 h76
  text "L" at -1263.61,18547.59 h76
  text "I" at -1225.27,18547.59 h76
  text "M" at -1205.27,18547.59 h76
  text "I" at -1148.58,18547.59 h76
  text "T" at -1128.58,18547.59 h76
  text "E" at -1085.24,18547.59 h76
  text "D" at -1038.56,18547.59 h76
  text "A" at -970.21,18547.59 h76
  text "N" at -923.53,18547.59 h76
  text "D" at -873.52,18547.59 h76
  text "M" at -803.5,18547.59 h76
  text "A" at -745.15,18547.59 h76
  text "Y" at -700.14,18547.59 h76
  text "ZONE" at 26955,18470 h60
  text "REV" at 27285,18470 h60
  text "DATE" at 29705,18470 h60
  text "B" at -2688,18467.57 h76
  text "E" at -2641.32,18467.57 h76
  text "F" at -2574.64,18467.57 h76
  text "R" at -2531.29,18467.57 h76
  text "E" at -2481.28,18467.57 h76
  text "E" at -2436.27,18467.57 h76
  text "L" at -2389.59,18467.57 h76
  text "Y" at -2351.25,18467.57 h76
  text "D" at -2284.57,18467.57 h76
  text "I" at -2234.55,18467.57 h76
  text "S" at -2216.22,18467.57 h76
  text "T" at -2169.54,18467.57 h76
  text "R" at -2126.88,18467.57 h76
  text "I" at -2078.54,18467.57 h76
  text "B" at -2058.53,18467.57 h76
  text "U" at -2011.86,18467.57 h76
  text "T" at -1961.84,18467.57 h76
  text "E" at -1918.5,18467.57 h76
  text "D" at -1871.82,18467.57 h76
  text "I" at -1803.47,18467.57 h76
  text "N" at -1783.47,18467.57 h76
  text "W" at -1716.78,18467.57 h76
  text "H" at -1648.43,18467.57 h76
  text "O" at -1600.09,18467.57 h76
  text "L" at -1545.07,18467.57 h76
  text "E" at -1506.73,18467.57 h76
  text "." at -1460.05,18467.57 h76
  text "N" at -1421.71,18467.57 h76
  text "O" at -1371.7,18467.57 h76
  text "R" at -1296.68,18467.57 h76
  text "I" at -1248.33,18467.57 h76
  text "G" at -1228.33,18467.57 h76
  text "H" at -1173.32,18467.57 h76
  text "T" at -1124.97,18467.57 h76
  text "S" at -1081.63,18467.57 h76
  text "A" at -1016.61,18467.57 h76
  text "R" at -969.93,18467.57 h76
  text "E" at -919.92,18467.57 h76
  text "DESCRIPTION" at 28300,18465 h60
  text "APPROVED" at 30210,18465 h60
  text "R" at -2688,18387.55 h76
  text "E" at -2637.99,18387.55 h76
  text "S" at -2591.31,18387.55 h76
  text "E" at -2544.63,18387.55 h76
  text "R" at -2497.95,18387.55 h76
  text "V" at -2447.94,18387.55 h76
  text "E" at -2401.26,18387.55 h76
  text "D" at -2354.58,18387.55 h76
  text "O" at -2286.23,18387.55 h76
  text "R" at -2231.22,18387.55 h76
  text "E" at -2161.2,18387.55 h76
  text "X" at -2114.52,18387.55 h76
  text "P" at -2069.51,18387.55 h76
  text "R" at -2022.83,18387.55 h76
  text "E" at -1972.82,18387.55 h76
  text "S" at -1926.14,18387.55 h76
  text "S" at -1879.47,18387.55 h76
  text "O" at -1814.45,18387.55 h76
  text "R" at -1759.44,18387.55 h76
  text "I" at -1691.09,18387.55 h76
  text "M" at -1671.08,18387.55 h76
  text "P" at -1612.73,18387.55 h76
  text "L" at -1566.06,18387.55 h76
  text "I" at -1529.38,18387.55 h76
  text "E" at -1509.37,18387.55 h76
  text "D" at -1462.7,18387.55 h76
  text "W" at -1396.01,18387.55 h76
  text "A" at -1327.66,18387.55 h76
  text "R" at -1280.99,18387.55 h76
  text "A" at -1230.97,18387.55 h76
  text "N" at -1184.29,18387.55 h76
  text "T" at -1135.95,18387.55 h76
  text "E" at -1092.61,18387.55 h76
  text "E" at -1045.93,18387.55 h76
  text "G" at -984.68,18387.55 h76
  text "I" at -929.66,18387.55 h76
  text "V" at -909.66,18387.55 h76
  text "E" at -862.98,18387.55 h76
  text "N" at -816.3,18387.55 h76
  text "." at -767.96,18387.55 h76
  text "A" at 27315,18335 h60
  text "ORIGINAL" at 28375,18335 h60
  text "A" at -2900,15900 h250
  text "A" at 30775,15900 h250
  text "B" at -2900,10550 h250
  text "B" at 30775,10550 h250
  text "C" at -2900,5200 h250
  text "C" at 30775,5200 h250
  text "DWG. NO." at 30815,3744.9 h30 r270
  text ".PCB_DWG_NO" at 30725,3530 h50 r270
  text "REV:" at 30815,2734.9 h30 r270
  text "D" at -2900,-150 h250
  text "D" at 30775,-150 h250
  text "SIZE:" at 27680,-2311 h45
  text "CAGE CODE:" at 27925,-2311 h45
  text "DWG NO:" at 28925,-2311 h45
  text "REV:" at 30485,-2311 h45
  text ".PCB_DWG_NO" at 29235,-2451 h100
  text "B" at 27720,-2456 h100
  text ".CAGE_CODE" at 28095,-2466 h100
  text "SCALE:" at 27620,-2626 h45
  text "FILE NAME:" at 28225,-2626.1 h45
  text "SHEET:" at 29965,-2626.1 h45
  text ".Printout_Name" at -2644,-2647 h150
  text ".Printout_Name" at -2644,-2647 h150
  text ".Printout_Name" at -2644,-2647 h150
  text ".PCB_FILE_NAME_NO_PATH" at 28568,-2671.1 h60
  text ".PCB_SCALE" at 27890,-2676 h60
  text "OF" at 30415,-2676.1 h45
  text "DOC-104 REV A" at -2700,-2742.1 h20
  text "DOC-104 REV A" at -2700,-2742.1 h20
  text "DOC-104 REV A" at -2700,-2742.1 h20
  text "1" at 1525,-2925 h250
  text "2" at 9900,-2925 h250
  text "3" at 18250,-2925 h250
  text "4" at 26600,-2925 h250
